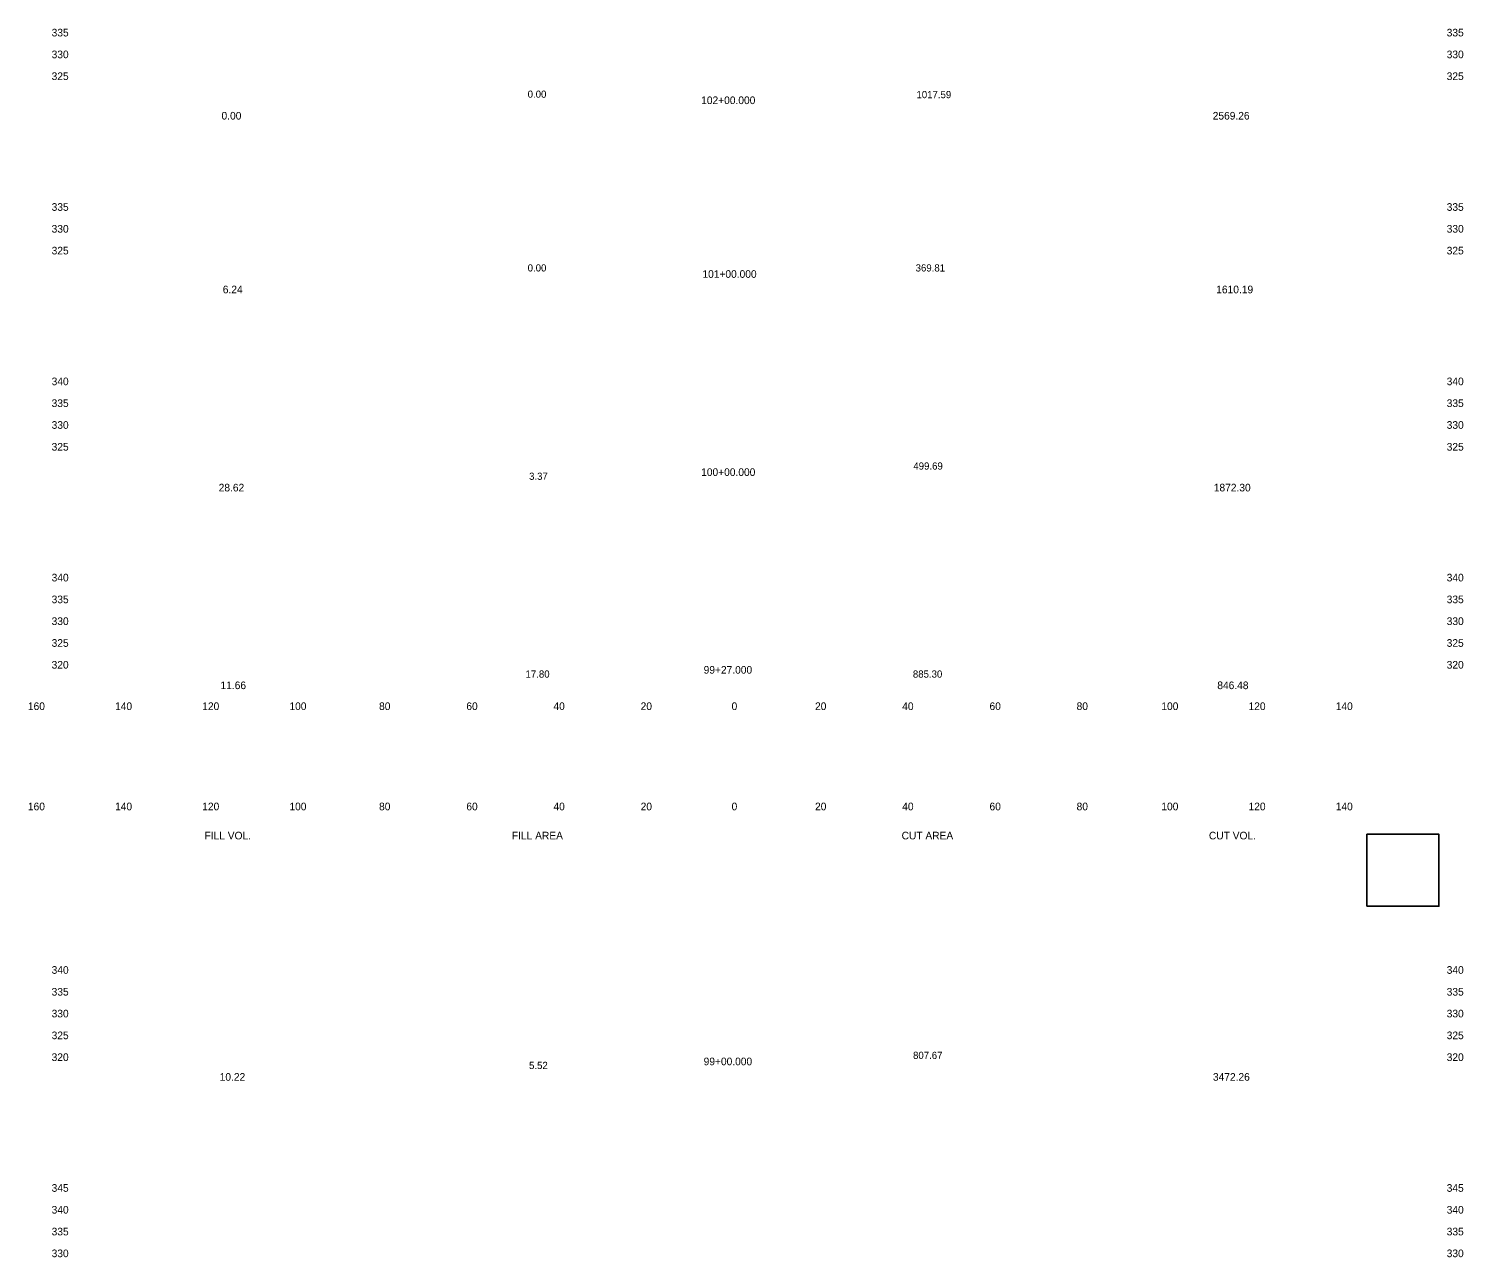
# Model space of a CAD drawing. Extents: x 21477 to 21806, y 6470 to 11049.
# Drawn here: x 21477.1 to 21806.1, y 7034.8 to 7316.6 of the extents above; entities that cross this region are included whole.
import ezdxf

# ---------------------------------------------------------------- set-up
doc = ezdxf.new("R2010")
doc.units = 0
for name, color, linetype in [('SHEET_CONSULTANT_STAMP', 7, 'Continuous'), ('XS_SHEET_EW_TX_AREA', 7, 'Continuous'), ('XS_SHEET_EW_TX_VOLUME', 7, 'Continuous'), ('XS_SHEET_LABELS_ELEVATION', 7, 'Continuous'), ('XS_SHEET_LABELS_OFFSET', 7, 'Continuous'), ('XS_SHEET_LABELS_STATION', 7, 'Continuous'), ('XS_SHEET_TX', 7, 'Continuous')]:
    doc.layers.add(name, color=color, linetype=linetype)

msp = doc.modelspace()

# ---------------------------------------------------------------- linework, layer by layer
at = {"layer": 'SHEET_CONSULTANT_STAMP'}
msp.add_lwpolyline([(21784.04, 7115.34), (21800.54, 7115.34), (21800.54, 7131.84), (21784.04, 7131.84)], close=True, dxfattribs=at)

# ---------------------------------------------------------------- texts
at = {"layer": 'XS_SHEET_EW_TX_AREA'}
for s, p in [(' 0.00 ', (21590.92, 7300.77)), (' 1017.59 ', (21680.1, 7300.67)), (' 0.00 ', (21590.92, 7260.92)), (' 369.81 ', (21679.91, 7260.92)), (' 499.69 ', (21679.39, 7215.48)), (' 3.37 ', (21591.24, 7213.14)), (' 17.80 ', (21590.43, 7167.77)), (' 885.30 ', (21679.28, 7167.77)), (' 807.67 ', (21679.32, 7080.31)), (' 5.52 ', (21591.24, 7078))]:
    msp.add_text(s, height=1.65, dxfattribs=at).set_placement(p)
at = {"layer": 'XS_SHEET_EW_TX_VOLUME'}
for s, p in [(' 0.00 ', (21520.66, 7295.77)), (' 2569.26 ', (21748.02, 7295.77)), (' 6.24 ', (21520.95, 7255.92)), (' 1610.19 ', (21748.83, 7255.92)), (' 28.62 ', (21520.01, 7210.48)), (' 1872.30 ', (21748.27, 7210.48)), (' 11.66 ', (21520.43, 7165.13)), (' 846.48 ', (21749.07, 7165.13)), (' 10.22 ', (21520.24, 7075.31)), (' 3472.26 ', (21748.07, 7075.31))]:
    msp.add_text(s, height=1.75, dxfattribs=at).set_placement(p)
at = {"layer": 'XS_SHEET_LABELS_ELEVATION'}
for s, p in [('  335  ', (21481.04, 7314.84)), ('  335  ', (21801.04, 7314.84)), ('  330  ', (21481.04, 7309.84)), ('  330  ', (21801.04, 7309.84)), ('  325  ', (21481.04, 7304.84)), ('  325  ', (21801.04, 7304.84)), ('  335  ', (21481.04, 7274.84)), ('  335  ', (21801.04, 7274.84)), ('  330  ', (21481.04, 7269.84)), ('  330  ', (21801.04, 7269.84)), ('  325  ', (21481.04, 7264.84)), ('  325  ', (21801.04, 7264.84)), ('  340  ', (21481.04, 7234.84)), ('  340  ', (21801.04, 7234.84)), ('  335  ', (21481.04, 7229.84)), ('  335  ', (21801.04, 7229.84)), ('  330  ', (21481.04, 7224.84)), ('  330  ', (21801.04, 7224.84)), ('  325  ', (21481.04, 7219.84)), ('  325  ', (21801.04, 7219.84)), ('  340  ', (21481.04, 7189.84)), ('  340  ', (21801.04, 7189.84)), ('  335  ', (21481.04, 7184.84)), ('  335  ', (21801.04, 7184.84)), ('  330  ', (21481.04, 7179.84)), ('  330  ', (21801.04, 7179.84)), ('  325  ', (21481.04, 7174.84)), ('  325  ', (21801.04, 7174.84)), ('  320  ', (21481.04, 7169.84)), ('  320  ', (21801.04, 7169.84)), ('  340  ', (21481.04, 7099.84)), ('  340  ', (21801.04, 7099.84)), ('  335  ', (21481.04, 7094.84)), ('  335  ', (21801.04, 7094.84)), ('  330  ', (21481.04, 7089.84)), ('  330  ', (21801.04, 7089.84)), ('  325  ', (21481.04, 7084.84)), ('  325  ', (21801.04, 7084.84)), ('  320  ', (21481.04, 7079.84)), ('  320  ', (21801.04, 7079.84)), ('  345  ', (21481.04, 7049.84)), ('  345  ', (21801.04, 7049.84)), ('  340  ', (21481.04, 7044.84)), ('  340  ', (21801.04, 7044.84)), ('  335  ', (21481.04, 7039.84)), ('  335  ', (21801.04, 7039.84)), ('  330  ', (21481.04, 7034.84)), ('  330  ', (21801.04, 7034.84))]:
    msp.add_text(s, height=1.75, dxfattribs=at).set_placement(p)
at = {"layer": 'XS_SHEET_LABELS_OFFSET'}
for s, p in [('  160  ', (21475.6, 7160.34)), ('  140  ', (21495.59, 7160.34)), ('  120  ', (21515.59, 7160.34)), ('  100  ', (21535.59, 7160.34)), ('  80  ', (21556.15, 7160.34)), ('  60  ', (21576.17, 7160.34)), ('  40  ', (21596.15, 7160.34)), ('  20  ', (21616.15, 7160.34)), ('  0  ', (21637.01, 7160.34)), ('  0  ', (21637.01, 7160.34)), ('  20  ', (21656.15, 7160.34)), ('  40  ', (21676.15, 7160.34)), ('  60  ', (21696.17, 7160.34)), ('  80  ', (21716.15, 7160.34)), ('  100  ', (21735.59, 7160.34)), ('  120  ', (21755.59, 7160.34)), ('  140  ', (21775.59, 7160.34)), ('  160  ', (21475.6, 7137.34)), ('  140  ', (21495.59, 7137.34)), ('  120  ', (21515.59, 7137.34)), ('  100  ', (21535.59, 7137.34)), ('  80  ', (21556.15, 7137.34)), ('  60  ', (21576.17, 7137.34)), ('  40  ', (21596.15, 7137.34)), ('  20  ', (21616.15, 7137.34)), ('  0  ', (21637.01, 7137.34)), ('  0  ', (21637.01, 7137.34)), ('  20  ', (21656.15, 7137.34)), ('  40  ', (21676.15, 7137.34)), ('  60  ', (21696.17, 7137.34)), ('  80  ', (21716.15, 7137.34)), ('  100  ', (21735.59, 7137.34)), ('  120  ', (21755.59, 7137.34)), ('  140  ', (21775.59, 7137.34))]:
    msp.add_text(s, height=1.75, dxfattribs=at).set_placement(p)
at = {"layer": 'XS_SHEET_LABELS_STATION'}
for s, p in [('  102+00.000  ', (21630.03, 7299.32)), ('  101+00.000  ', (21630.32, 7259.47)), ('  100+00.000  ', (21630.03, 7214.03)), ('  99+27.000  ', (21630.6, 7168.68)), ('  99+00.000  ', (21630.6, 7078.86))]:
    msp.add_text(s, height=1.75, dxfattribs=at).set_placement(p)
at = {"layer": 'XS_SHEET_TX'}
for s, p in [('FILL VOL.', (21517.41, 7130.67)), ('FILL AREA', (21587.92, 7130.67)), ('CUT AREA', (21677.31, 7130.67)), ('CUT VOL.', (21747.8, 7130.67))]:
    msp.add_text(s, height=1.75, dxfattribs=at).set_placement(p)

doc.saveas('drawing.dxf')
